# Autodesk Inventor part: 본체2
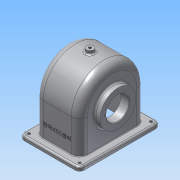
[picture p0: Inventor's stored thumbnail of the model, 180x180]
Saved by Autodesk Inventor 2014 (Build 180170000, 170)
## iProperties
Created: 2016-01
Part Number: 본체2
Material: 알루미늄 6061
Document SubType Name: Modeling
Designer: User
Mass: 809.57 g
Surface Area: 999.664 cm^2
Volume: 298.734 cm^3
Density: 2.71 g/cm^3
Appearance: 알루미늄 - 평지
Author: User
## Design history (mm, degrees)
sketch "스케치1"
  geometry: L1 (-57, 0)-(57, 0); L2 (57, 0)-(57, -64); L3 (57, -64)-(-57, -64); L4 (-57, -64)-(-57, 0); C1 r 57 at (0, 0); 2 further points
  constraints: 8 end point, 2 coincident, 2 parallel, 1 centre point, 1 horizontal, 1 midpoint, 1 perpendicular
  dimensions: "d0" = 114 diameter of C1; "d1" = 114 distance of L2.end L3.end; "d2" = 64 distance of L1.end L2.end
extrude "돌출1" new body sketch "스케치1" stored distance "d3" = 77; taper "d4" = 0 deg
feature "쉘1" dims "d7" = 6
sketch "스케치3"
  geometry: L1 (114, 0)-(114, -77) reference; L2 (0, 0)-(114, 0) reference; L3 (0, 0)-(0, -77) reference; L4 (114, -77)-(0, -77) reference; L5 (-13, 13.5)-(127, 13.5); L6 (127, 13.5)-(127, -90.5); L7 (127, -90.5)-(-13, -90.5); L8 (-13, -90.5)-(-13, 13.5); 3 further points
  constraints: 8 end point, 2 midpoint, 2 parallel, 1 horizontal, 1 horizontal alignment, 1 perpendicular, 1 vertical alignment
  dimensions: "d8" = 140 distance of L5.start L5.end; "d9" = 104 distance of L5.end L6.end
extrude "돌출2" join sketch "스케치3" distance "d10" = 7; taper "d11" = 0 deg
fillet "모깎기1" dims "d12" = 14
node "작업 평면1"
sketch "스케치6"
  geometry: C1 r 6 at (0, 0); 1 further point
  constraints: 1 centre point, 1 coincident
  dimensions: "d36" = 12 diameter of C1
extrude "돌출4" join sketch "스케치6" stored distance "d37" = 10; taper "d38" = 0 deg
hole "구멍2" diameter "d41" = 4.459; stored, may be unused: countersink angle "d45" = 90 deg, drill point angle "d47" = 118 deg; dims "d39" = 10, "d40" = 10, "d42" = 6, "d43" = 4, "d44" = 2, "d46" = 63
fillet "모깎기4" dims "d77" = 8
sketch "스케치9"
  geometry: A1 r 8 centre (119, 82.5) between (127, 82.5) and (119, 90.5) reference; A2 r 8 centre (-5, 82.5) between (-5, 90.5) and (-13, 82.5) reference; A3 r 8 centre (-5, -5.5) between (-13, -5.5) and (-5, -13.5) reference; A4 r 8 centre (119, -5.5) between (119, -13.5) and (127, -5.5) reference; 1 further point
hole "구멍5" sketch "스케치9" at (119, 82.5), (-5, 82.5), (119, -5.5), (-5, -5.5) diameter "d78" = 5; stored, may be unused: countersink angle "d82" = 90 deg, drill point angle "d84" = 118 deg; dims "d79" = 7, "d80" = 4, "d81" = 2, "d83" = 9
fillet "모깎기5" dims "d85" = 3
sketch "스케치10"
  geometry: L1 (49, 0)-(49, -57) reference; L2 (0, 0)-(49, 0) reference; L3 (0, -57)-(0, 0) reference; L4 (-1.387, -30.398)-(50.387, -30.398); L5 (50.387, -30.398)-(50.387, -37.602); L6 (50.387, -37.602)-(-1.387, -37.602); L7 (-1.387, -37.602)-(-1.387, -30.398); L8 (0, -34)-(49, -34); L9 (-19.5, -64)-(68.5, -64) reference; L10 (24.5, 0)-(24.5, -54); L11 (-14, 0)-(-14, -57) reference; L12 (68.5, -57)-(-19.5, -57) reference; 4 further points
  constraints: 4 end point, 4 midpoint, 2 point on line, 1 horizontal alignment, 1 perpendicular, 1 vertical alignment, 2 other
  dimensions: "d86" = 30 distance between parallel lines of L9 L8; "d87" = 38.5 distance between parallel lines of L11 L10
feature "엠보싱1" sketch "스케치10" dims "d8" = 140, "d9" = 104, "d88" = 0.5, "d89" = 0
sketch "스케치11"
  geometry: L1 (-51, -64)-(-51, 0) reference; L2 (51, -64)-(-51, -64) reference; L3 (51, 0)-(51, -64) reference; C1 r 20 at (0, -4) reference; A1 r 51 centre (0, 0) between (51, 0) and (-51, 0) reference
extrude "돌출5" cut sketch "스케치11" distance "d90" = 1; taper "d91" = 0 deg
sketch "스케치12"
  geometry: L1 (-51, -64)-(-51, 0) reference; L2 (51, -64)-(-51, -64) reference; L3 (51, 0)-(51, -64) reference; C1 r 38.908 at (0, -4) reference; A1 r 51 centre (0, 0) between (51, 0) and (-51, 0) reference
extrude "돌출6" cut sketch "스케치12" distance "d92" = 1; taper "d93" = 0 deg
sketch "스케치13"
  geometry: L1 (-4, 43.197)-(-4, -48.942); L2 (-64, -33.5)-(-64, 33.5) reference; L3 (16, 35.5)-(30.899, 35.5); L4 (24, 35.5)-(24, 19.5); L5 (24, 19.5)-(16, 19.5); L6 (16, 19.5)-(16, 35.5); L7 (0, 38.5)-(43, 38.5) reference; L8 (24, 19.5)-(39.943, 38.5); L9 (30.899, 35.5)-(33.416, 38.5); L10 (-4, 33.5)-(16, 33.5); L11 (-4, 38.5)-(33.416, 38.5); L12 (-4, 38.5)-(-4, 33.5); 1 further point
  constraints: 20 end point, 6 point on line, 3 parallel, 2 perpendicular, 1 collinear, 1 horizontal, 1 vertical
  dimensions: "d95" = 60 distance between parallel lines of L1 L2; "d96" = 20 distance between parallel lines of L1 L6; "d99" = 50 deg angle of L8 L5; "d100" = 5 distance between parallel lines of L8 L9; "d102" = 5 distance between parallel lines of L10 L11; "d103" = 56 diameter of L4 L1; "d104" = 19 distance between parallel lines of L11 L5; "d105" = 3 distance between parallel lines of L11 L3
revolve "회전3" stored, may be unused: angle "d106" = 90 deg
revolve "회전4" stored, may be unused: angle "d107" = 90 deg
sketch "스케치14"
  geometry: C1 r 20 at (0, -4) reference; C2 r 31 at (0, -4)
  constraints: 1 centre point, 1 coincident
  dimensions: "d108" = 62 diameter of C2
extrude "돌출7" join sketch "스케치14" distance "d109" = 10; taper "d110" = 0 deg
hole "구멍6" diameter "d113" = 40; stored, may be unused: countersink angle "d117" = 90 deg, drill point angle "d119" = 118 deg; dims "d111" = 10, "d112" = 10, "d114" = 6, "d115" = 4, "d116" = 2, "d118" = 8
chamfer "모따기3" distance "d120" = 1; stored, may be unused: second distance "d121" = 2, angle "d122" = 45 deg
fillet "모깎기6" dims "d123" = 3
sketch "스케치15"
  geometry: C1 r 31 at (0, 0) reference; 2 further points
  constraints: 1 vertical alignment
  dimensions: "d124" = 24 distance of C1.centre point (0, 24)
hole "구멍7" sketch "스케치15" at (0, 24) diameter "d125" = 2.459; stored, may be unused: countersink angle "d129" = 90 deg, drill point angle "d131" = 118 deg; dims "d126" = 6, "d127" = 4, "d128" = 2, "d130" = 8
sketch "스케치16"
  geometry: C1 r 21 at (0, 0) reference; 2 further points
  constraints: 1 vertical alignment
  dimensions: "d135" = 28 distance of C1.centre point (0, 28)
hole "구멍8" sketch "스케치16" at (0, 28) diameter "d136" = 2.459; stored, may be unused: countersink angle "d140" = 90 deg, drill point angle "d142" = 118 deg; dims "d137" = 7, "d138" = 4, "d139" = 2, "d141" = 9
fillet "모깎기7" dims "d146" = 9
fillet "모깎기8" dims "d147" = 3
fillet "모깎기9" dims "d148" = 1
node "솔리드1"
pattern_circular "원형 패턴3" dims angle "d133" = 360 deg
pattern_circular "원형 패턴4" dims angle "d144" = 360 deg
other parameters: "d35" = 63
